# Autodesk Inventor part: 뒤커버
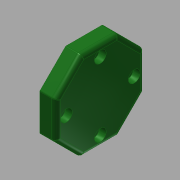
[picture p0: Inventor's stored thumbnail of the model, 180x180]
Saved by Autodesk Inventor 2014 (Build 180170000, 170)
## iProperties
Created: 2015-11
Part Number: 뒤커버
Material: 알루미늄 6061
Document SubType Name: Modeling
Designer: mduedu
Density: 1 g/cm^3
Appearance: Smooth - Dark Forest Green
Author: mduedu
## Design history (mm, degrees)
sketch "스케치5" dims "d66" = 60
  geometry: L1 (12.426, 30)-(30, 12.426); L2 (30, 12.426)-(30, -12.426); L3 (30, -12.426)-(12.426, -30); L4 (12.426, -30)-(-12.426, -30); L5 (-12.426, -30)-(-30, -12.426); L6 (-30, -12.426)-(-30, 12.426); L7 (-30, 12.426)-(-12.426, 30); L8 (-12.426, 30)-(12.426, 30); 4 further points
  constraints: 16 end point, 2 coincident, 2 vertical alignment, 1 midpoint, 19 other
extrude "돌출2" new body sketch "스케치5" distance "d67" = 11; taper "d68" = 0 deg
sketch "스케치6"
  geometry: C1 r 16 at (0, 0); 1 further point
  constraints: 1 centre point, 1 coincident
  dimensions: "d69" = 32 diameter of C1
extrude "돌출3" join sketch "스케치6" distance "d70" = 3; taper "d71" = 0 deg
hole "구멍5" diameter "d74" = 25; stored, may be unused: countersink angle "d78" = 90 deg, drill point angle "d80" = 0 deg; dims "d72" = 10, "d73" = 10, "d75" = 6, "d76" = 4, "d77" = 2, "d79" = 10
fillet "모깎기7" dims "d81" = 1
fillet "모깎기8" dims "d82" = 3
fillet "모깎기9" dims "d83" = 3
fillet "모깎기10" dims "d84" = 0.3
sketch "스케치7" dims "d85" = 46
  geometry: 3 further points
  constraints: 2 vertical alignment, 1 coincident, 2 other
hole "구멍6" sketch "스케치7" at (0, 23) diameter "d86" = 4.5; stored, may be unused: countersink angle "d90" = 90 deg, drill point angle "d92" = 0 deg; dims "d87" = 6, "d88" = 8, "d89" = 4.6, "d91" = 10
node "솔리드2"
pattern_circular "원형 패턴3" dims angle "d94" = 360 deg
